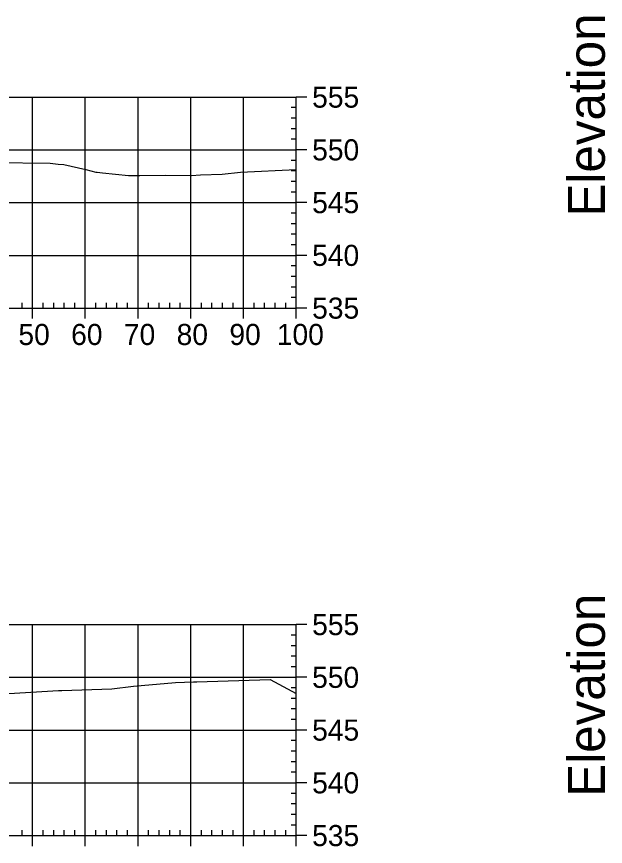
# Model space of a CAD drawing. Extents: x 708103 to 717568, y 374476 to 378707.
# Drawn here: x 710748.9 to 710860.6, y 377042.6 to 377199.9 of the extents above; entities that cross this region are included whole.
import ezdxf

# ---------------------------------------------------------------- set-up
doc = ezdxf.new("R2010")
doc.units = 0
for name, color, linetype in [('57', 7, 'Continuous'), ('60', 7, 'Continuous'), ('Existing', 7, 'Continuous')]:
    doc.layers.add(name, color=color, linetype=linetype)

msp = doc.modelspace()

# ---------------------------------------------------------------- linework, layer by layer
at = {"layer": '57'}
for p, q in [((710601.98, 377184.63), (710801.98, 377184.63)), ((710751.98, 377144.63), (710751.98, 377184.63)), ((710761.98, 377144.63), (710761.98, 377184.63)), ((710771.98, 377144.63), (710771.98, 377184.63)), ((710781.98, 377144.63), (710781.98, 377184.63)), ((710791.98, 377144.63), (710791.98, 377184.63)), ((710801.98, 377144.63), (710801.98, 377184.63)), ((710801.98, 377144.63), (710801.98, 377184.63)), ((710803.98, 377184.63), (710801.98, 377184.63)), ((710801.98, 377182.63), (710800.98, 377182.63)), ((710801.98, 377180.63), (710800.98, 377180.63)), ((710801.98, 377178.63), (710800.98, 377178.63)), ((710801.98, 377176.63), (710800.98, 377176.63)), ((710601.98, 377174.63), (710801.98, 377174.63)), ((710803.98, 377174.63), (710801.98, 377174.63)), ((710801.98, 377172.63), (710800.98, 377172.63)), ((710801.98, 377170.63), (710800.98, 377170.63)), ((710801.98, 377168.63), (710800.98, 377168.63)), ((710801.98, 377166.63), (710800.98, 377166.63)), ((710601.98, 377164.63), (710801.98, 377164.63)), ((710803.98, 377164.63), (710801.98, 377164.63)), ((710801.98, 377162.63), (710800.98, 377162.63)), ((710801.98, 377160.63), (710800.98, 377160.63)), ((710801.98, 377158.63), (710800.98, 377158.63)), ((710801.98, 377156.63), (710800.98, 377156.63)), ((710601.98, 377154.63), (710801.98, 377154.63)), ((710803.98, 377154.63), (710801.98, 377154.63)), ((710801.98, 377152.63), (710800.98, 377152.63)), ((710801.98, 377150.63), (710800.98, 377150.63)), ((710801.98, 377148.63), (710800.98, 377148.63)), ((710801.98, 377146.63), (710800.98, 377146.63)), ((710749.98, 377144.63), (710749.98, 377145.63)), ((710753.98, 377144.63), (710753.98, 377145.63)), ((710755.98, 377144.63), (710755.98, 377145.63)), ((710757.98, 377144.63), (710757.98, 377145.63)), ((710759.98, 377144.63), (710759.98, 377145.63)), ((710763.98, 377144.63), (710763.98, 377145.63)), ((710765.98, 377144.63), (710765.98, 377145.63)), ((710767.98, 377144.63), (710767.98, 377145.63)), ((710769.98, 377144.63), (710769.98, 377145.63)), ((710773.98, 377144.63), (710773.98, 377145.63)), ((710775.98, 377144.63), (710775.98, 377145.63)), ((710777.98, 377144.63), (710777.98, 377145.63)), ((710779.98, 377144.63), (710779.98, 377145.63)), ((710783.98, 377144.63), (710783.98, 377145.63)), ((710785.98, 377144.63), (710785.98, 377145.63)), ((710787.98, 377144.63), (710787.98, 377145.63)), ((710789.98, 377144.63), (710789.98, 377145.63)), ((710793.98, 377144.63), (710793.98, 377145.63)), ((710795.98, 377144.63), (710795.98, 377145.63)), ((710797.98, 377144.63), (710797.98, 377145.63)), ((710799.98, 377144.63), (710799.98, 377145.63)), ((710601.98, 377144.63), (710801.98, 377144.63)), ((710601.98, 377144.63), (710801.98, 377144.63)), ((710751.98, 377142.63), (710751.98, 377144.63)), ((710761.98, 377142.63), (710761.98, 377144.63)), ((710771.98, 377142.63), (710771.98, 377144.63)), ((710781.98, 377142.63), (710781.98, 377144.63)), ((710791.98, 377142.63), (710791.98, 377144.63)), ((710801.98, 377142.63), (710801.98, 377144.63)), ((710803.98, 377144.63), (710801.98, 377144.63)), ((710601.98, 377084.63), (710801.98, 377084.63)), ((710751.98, 377044.63), (710751.98, 377084.63)), ((710761.98, 377044.63), (710761.98, 377084.63)), ((710771.98, 377044.63), (710771.98, 377084.63)), ((710781.98, 377044.63), (710781.98, 377084.63)), ((710791.98, 377044.63), (710791.98, 377084.63)), ((710801.98, 377044.63), (710801.98, 377084.63)), ((710801.98, 377044.63), (710801.98, 377084.63)), ((710803.98, 377084.63), (710801.98, 377084.63)), ((710801.98, 377082.63), (710800.98, 377082.63)), ((710801.98, 377080.63), (710800.98, 377080.63)), ((710801.98, 377078.63), (710800.98, 377078.63)), ((710801.98, 377076.63), (710800.98, 377076.63)), ((710601.98, 377074.63), (710801.98, 377074.63)), ((710803.98, 377074.63), (710801.98, 377074.63)), ((710801.98, 377072.63), (710800.98, 377072.63)), ((710801.98, 377070.63), (710800.98, 377070.63)), ((710801.98, 377068.63), (710800.98, 377068.63)), ((710801.98, 377066.63), (710800.98, 377066.63)), ((710601.98, 377064.63), (710801.98, 377064.63)), ((710803.98, 377064.63), (710801.98, 377064.63)), ((710801.98, 377062.63), (710800.98, 377062.63)), ((710801.98, 377060.63), (710800.98, 377060.63)), ((710801.98, 377058.63), (710800.98, 377058.63)), ((710801.98, 377056.63), (710800.98, 377056.63)), ((710601.98, 377054.63), (710801.98, 377054.63)), ((710803.98, 377054.63), (710801.98, 377054.63)), ((710801.98, 377052.63), (710800.98, 377052.63)), ((710801.98, 377050.63), (710800.98, 377050.63)), ((710801.98, 377048.63), (710800.98, 377048.63)), ((710801.98, 377046.63), (710800.98, 377046.63)), ((710601.98, 377044.63), (710801.98, 377044.63)), ((710601.98, 377044.63), (710801.98, 377044.63)), ((710749.98, 377044.63), (710749.98, 377045.63)), ((710751.98, 377042.63), (710751.98, 377044.63)), ((710753.98, 377044.63), (710753.98, 377045.63)), ((710755.98, 377044.63), (710755.98, 377045.63)), ((710757.98, 377044.63), (710757.98, 377045.63)), ((710759.98, 377044.63), (710759.98, 377045.63)), ((710761.98, 377042.63), (710761.98, 377044.63)), ((710763.98, 377044.63), (710763.98, 377045.63)), ((710765.98, 377044.63), (710765.98, 377045.63)), ((710767.98, 377044.63), (710767.98, 377045.63)), ((710769.98, 377044.63), (710769.98, 377045.63)), ((710771.98, 377042.63), (710771.98, 377044.63)), ((710773.98, 377044.63), (710773.98, 377045.63)), ((710775.98, 377044.63), (710775.98, 377045.63)), ((710777.98, 377044.63), (710777.98, 377045.63)), ((710779.98, 377044.63), (710779.98, 377045.63)), ((710781.98, 377042.63), (710781.98, 377044.63)), ((710783.98, 377044.63), (710783.98, 377045.63)), ((710785.98, 377044.63), (710785.98, 377045.63)), ((710787.98, 377044.63), (710787.98, 377045.63)), ((710789.98, 377044.63), (710789.98, 377045.63)), ((710791.98, 377042.63), (710791.98, 377044.63)), ((710793.98, 377044.63), (710793.98, 377045.63)), ((710795.98, 377044.63), (710795.98, 377045.63)), ((710797.98, 377044.63), (710797.98, 377045.63)), ((710799.98, 377044.63), (710799.98, 377045.63)), ((710801.98, 377042.63), (710801.98, 377044.63)), ((710803.98, 377044.63), (710801.98, 377044.63))]:
    msp.add_line(p, q, dxfattribs=at)
at = {"layer": 'Existing'}
for points in [[(710744.85, 377172.24), (710755.3, 377172.1), (710755.79, 377172.06), (710756.8, 377171.93), (710757.88, 377171.88), (710762.1, 377170.93), (710763.95, 377170.43), (710764.23, 377170.42), (710765.25, 377170.3), (710770.17, 377169.76), (710772.29, 377169.77), (710777.23, 377169.83), (710782.13, 377169.74), (710783.79, 377169.88), (710787.93, 377169.99), (710791.43, 377170.41), (710801.98, 377170.9)], [(710747.49, 377071.57), (710756.9, 377072.15), (710757.5, 377072.16), (710766.98, 377072.43), (710771.1, 377072.94), (710779.07, 377073.68), (710782.52, 377073.77), (710782.57, 377073.77), (710782.81, 377073.78), (710783.11, 377073.79), (710797.03, 377074.22), (710801.98, 377071.56)]]:
    msp.add_lwpolyline(points, dxfattribs=at)

# ---------------------------------------------------------------- texts
at = {"layer": '57'}
for s, p in [('555', (710804.98, 377182.63)), ('550', (710804.98, 377172.63)), ('545', (710804.98, 377162.63)), ('540', (710804.98, 377152.63)), ('535', (710804.98, 377142.63)), ('50', (710749.29, 377137.63)), ('60', (710759.29, 377137.63)), ('70', (710769.29, 377137.63)), ('80', (710779.29, 377137.63)), ('90', (710789.29, 377137.63)), ('100', (710798.28, 377137.63)), ('555', (710804.98, 377082.63)), ('550', (710804.98, 377072.63)), ('545', (710804.98, 377062.63)), ('540', (710804.98, 377052.63)), ('535', (710804.98, 377042.63))]:
    msp.add_text(s, height=4, dxfattribs=at).set_placement(p)
at = {"layer": '60'}
for p in [(710860.48, 377161.99), (710860.48, 377051.99)]:
    msp.add_text('Elevation', height=7, rotation=90, dxfattribs=at).set_placement(p)

doc.saveas('drawing.dxf')
